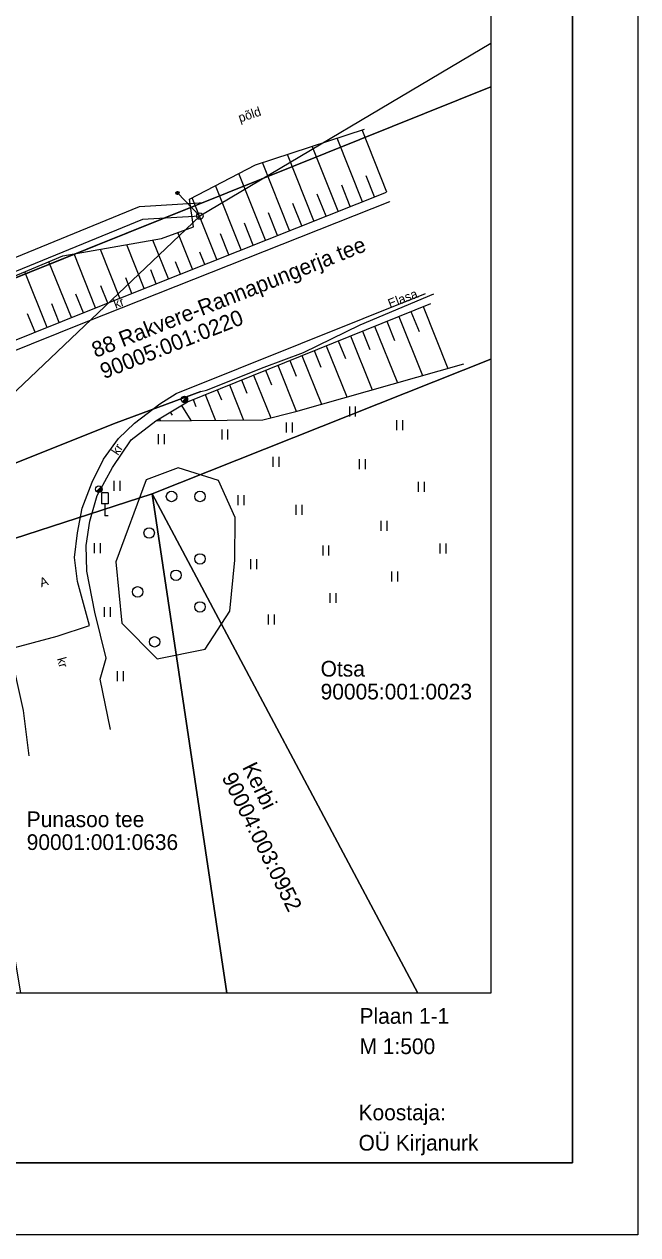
# Model space of a CAD drawing. Extents: x 655676 to 655781, y 6568872 to 6569021.
# Drawn here: x 655734.4 to 655781.4, y 6568872.1 to 6568964.7 of the extents above; entities that cross this region are included whole.
import ezdxf

# ---------------------------------------------------------------- set-up
doc = ezdxf.new("R2010")
doc.units = 0
for name, color, linetype in [('HALJASTUS', 7, 'Continuous'), ('KASUTUSALA', 7, 'Continuous'), ('LIIKLUS', 7, 'Continuous'), ('MPOHULIIN', 7, 'Continuous'), ('OL_SIDE', 7, 'Continuous'), ('PIIR', 7, 'Continuous'), ('POST', 7, 'Continuous'), ('PR_SIDE', 7, 'Continuous'), ('RELJEEF', 7, 'Continuous'), ('SITRASS', 7, 'Continuous'), ('TEE', 7, 'Continuous'), ('VORMISTUS', 7, 'Continuous')]:
    doc.layers.add(name, color=color, linetype=linetype)

msp = doc.modelspace()

# ---------------------------------------------------------------- linework, layer by layer
at = {"layer": 'HALJASTUS'}
for p, q in [((655759.288, 6568935.45), (655759.288, 6568934.689)), ((655759.743, 6568935.45), (655759.743, 6568934.689)), ((655754.44, 6568934.225), (655754.44, 6568933.464)), ((655754.895, 6568934.225), (655754.895, 6568933.464)), ((655762.911, 6568934.396), (655762.911, 6568933.635)), ((655763.366, 6568934.396), (655763.366, 6568933.635)), ((655744.644, 6568933.334), (655744.644, 6568932.573)), ((655745.099, 6568933.334), (655745.099, 6568932.573)), ((655749.509, 6568933.676), (655749.509, 6568932.915)), ((655749.964, 6568933.676), (655749.964, 6568932.915)), ((655753.431, 6568931.585), (655753.431, 6568930.824)), ((655753.886, 6568931.585), (655753.886, 6568930.824)), ((655760.045, 6568931.417), (655760.045, 6568930.656)), ((655760.5, 6568931.417), (655760.5, 6568930.656)), ((655741.241, 6568929.758), (655741.241, 6568928.997)), ((655741.696, 6568929.758), (655741.696, 6568928.997)), ((655764.563, 6568929.677), (655764.563, 6568928.916)), ((655765.018, 6568929.677), (655765.018, 6568928.916)), ((655750.746, 6568928.665), (655750.746, 6568927.904)), ((655751.201, 6568928.665), (655751.201, 6568927.904)), ((655755.189, 6568927.921), (655755.189, 6568927.16)), ((655755.644, 6568927.921), (655755.644, 6568927.16)), ((655761.712, 6568926.703), (655761.712, 6568925.942)), ((655762.167, 6568926.703), (655762.167, 6568925.942)), ((655739.746, 6568924.987), (655739.746, 6568924.226)), ((655740.202, 6568924.987), (655740.202, 6568924.226)), ((655766.215, 6568924.958), (655766.215, 6568924.197)), ((655766.671, 6568924.958), (655766.671, 6568924.197)), ((655757.245, 6568924.804), (655757.245, 6568924.043)), ((655757.7, 6568924.804), (655757.7, 6568924.043)), ((655751.719, 6568923.761), (655751.719, 6568922.999)), ((655752.174, 6568923.761), (655752.174, 6568922.999)), ((655762.514, 6568922.819), (655762.514, 6568922.058)), ((655762.969, 6568922.819), (655762.969, 6568922.058)), ((655757.794, 6568921.171), (655757.794, 6568920.41)), ((655758.249, 6568921.171), (655758.249, 6568920.41)), ((655740.51, 6568920.099), (655740.51, 6568919.338)), ((655740.965, 6568920.099), (655740.965, 6568919.338)), ((655753.073, 6568919.523), (655753.073, 6568918.762)), ((655753.528, 6568919.523), (655753.528, 6568918.762)), ((655741.493, 6568915.197), (655741.493, 6568914.436)), ((655741.948, 6568915.197), (655741.948, 6568914.436))]:
    msp.add_line(p, q, dxfattribs=at)
msp.add_lwpolyline([(655741.403, 6568923.562), (655741.853, 6568918.871), (655744.562, 6568916.139), (655748.235, 6568916.874), (655750.121, 6568919.789), (655750.513, 6568923.685), (655750.537, 6568926.943), (655749.264, 6568929.785), (655746.178, 6568930.741), (655743.73, 6568929.834)], close=True, dxfattribs=at)
for centre in [(655745.664, 6568928.56), (655747.844, 6568928.56), (655743.95, 6568925.767), (655747.844, 6568923.783), (655746.007, 6568922.533), (655743.068, 6568921.259), (655747.844, 6568920.108), (655744.366, 6568917.437)]:
    msp.add_circle(centre, 0.4, dxfattribs=at)
at = {"layer": 'KASUTUSALA'}
msp.add_lwpolyline([(655709.743, 6568937.057), (655743.212, 6568950.756), (655747.77, 6568951.021), (655748.021, 6568951.036), (655709.655, 6568935.641), (655709.573, 6568935.853)], close=True, dxfattribs=at)
at = {"layer": 'LIIKLUS'}
for p, q in [((655740.3, 6568928.84), (655740.3, 6568927.99)), ((655740.8, 6568928.84), (655740.3, 6568928.84)), ((655740.8, 6568928.84), (655740.8, 6568927.99)), ((655740.8, 6568927.99), (655740.3, 6568927.99)), ((655740.55, 6568927.99), (655740.55, 6568927.09)), ((655740.8, 6568927.09), (655740.55, 6568927.09))]:
    msp.add_line(p, q, dxfattribs=at)
at = {"layer": 'MPOHULIIN'}
msp.add_lwpolyline([(655770.139, 6568963.217), (655747.828, 6568950.023), (655716.621, 6568920.405), (655692.519, 6568890.558)], dxfattribs=at)
at = {"layer": 'OL_SIDE'}
msp.add_line((655770.139, 6568963.217), (655747.828, 6568950.023), dxfattribs=at)
at = {"layer": 'PIIR'}
for p, q in [((655687.639, 6568926.806), (655770.139, 6568959.911)), ((655770.139, 6568959.911), (655687.639, 6568926.806))]:
    msp.add_line(p, q, dxfattribs=at)
for points in [[(655687.639, 6568907.034), (655727.79, 6568923.46), (655744.18, 6568928.77), (655770.139, 6568939.075)], [(655770.139, 6568939.075), (655744.18, 6568928.77), (655764.524, 6568890.558)], [(655749.911, 6568890.558), (655744.18, 6568928.77), (655727.79, 6568923.46), (655731.26, 6568907.53), (655734.086, 6568890.558)], [(655764.524, 6568890.558), (655744.18, 6568928.77), (655749.911, 6568890.558)]]:
    msp.add_lwpolyline(points, dxfattribs=at)
at = {"layer": 'POST'}
for p, q in [((655746.471, 6568935.814), (655746.825, 6568936.167)), ((655739.922, 6568928.944), (655740.276, 6568929.297))]:
    msp.add_line(p, q, dxfattribs=at)
msp.add_lwpolyline([(655746.116, 6568951.787), (655747.828, 6568950.023)], dxfattribs=at)
for centre, radius in [((655746.116, 6568951.787), 0.125), ((655746.116, 6568951.787), 0.105), ((655746.116, 6568951.787), 0.0851), ((655746.116, 6568951.787), 0.0651), ((655746.116, 6568951.787), 0.0451), ((655746.116, 6568951.787), 0.0251), ((655746.116, 6568951.787), 0.00511), ((655747.828, 6568950.023), 0.25), ((655747.828, 6568950.023), 0.0234), ((655746.648, 6568935.991), 0.25), ((655740.099, 6568929.121), 0.25)]:
    msp.add_circle(centre, radius, dxfattribs=at)
for centre, radius, start, end in [((655746.648, 6568935.991), 0.225, 224.85406, 45.03563), ((655746.648, 6568935.991), 0.2, 224.84272, 45.04698), ((655746.648, 6568935.991), 0.175, 224.82813, 45.06157), ((655746.648, 6568935.991), 0.15, 224.80867, 45.08103), ((655746.648, 6568935.991), 0.125, 224.78144, 45.10826), ((655746.648, 6568935.991), 0.1, 224.74058, 45.14911), ((655746.648, 6568935.991), 0.075, 224.67249, 45.2172), ((655746.648, 6568935.991), 0.05, 224.53632, 45.35338), ((655746.648, 6568935.991), 0.025, 224.12776, 45.76193), ((655740.099, 6568929.121), 0.225, 224.85406, 45.03563), ((655740.099, 6568929.121), 0.2, 224.84272, 45.04698), ((655740.099, 6568929.121), 0.175, 224.82813, 45.06157), ((655740.099, 6568929.121), 0.15, 224.80867, 45.08103), ((655740.099, 6568929.121), 0.125, 224.78144, 45.10826), ((655740.099, 6568929.121), 0.1, 224.74058, 45.14911), ((655740.099, 6568929.121), 0.075, 224.67249, 45.2172), ((655740.099, 6568929.121), 0.05, 224.53632, 45.35338), ((655740.099, 6568929.121), 0.025, 224.12776, 45.76193)]:
    msp.add_arc(centre, radius, start, end, dxfattribs=at)
at = {"layer": 'PR_SIDE'}
msp.add_lwpolyline([(655747.828, 6568950.023), (655743.437, 6568949.768), (655710.653, 6568936.35), (655710.6, 6568935.972), (655716.621, 6568920.405)], dxfattribs=at)
at = {"layer": 'RELJEEF'}
for p, q in [((655762.147, 6568951.86), (655760.257, 6568956.613)), ((655760.289, 6568951.121), (655758.353, 6568955.989)), ((655756.572, 6568949.643), (655754.545, 6568954.74)), ((655758.43, 6568950.382), (655756.449, 6568955.364)), ((655754.713, 6568948.904), (655752.641, 6568954.116)), ((655752.855, 6568948.165), (655750.822, 6568953.277)), ((655761.218, 6568951.491), (655760.58, 6568953.094)), ((655750.996, 6568947.426), (655749.038, 6568952.35)), ((655759.359, 6568950.751), (655758.706, 6568952.393)), ((655749.138, 6568946.686), (655747.254, 6568951.424)), ((655755.642, 6568949.273), (655754.959, 6568950.991)), ((655757.501, 6568950.012), (655756.833, 6568951.692)), ((655753.784, 6568948.534), (655753.094, 6568950.269)), ((655751.926, 6568947.795), (655751.26, 6568949.468)), ((655745.421, 6568945.208), (655744.24, 6568948.177)), ((655747.28, 6568945.947), (655746.159, 6568948.764)), ((655750.067, 6568947.056), (655749.427, 6568948.666)), ((655739.846, 6568942.991), (655738.204, 6568947.121)), ((655741.704, 6568943.73), (655740.216, 6568947.473)), ((655743.563, 6568944.469), (655742.228, 6568947.825)), ((655748.209, 6568946.317), (655747.838, 6568947.25)), ((655737.989, 6568942.247), (655736.272, 6568946.525)), ((655746.35, 6568945.578), (655745.974, 6568946.523)), ((655736.133, 6568941.502), (655734.427, 6568945.753)), ((655742.633, 6568944.1), (655742.163, 6568945.283)), ((655744.492, 6568944.839), (655744.073, 6568945.893)), ((655740.775, 6568943.361), (655740.253, 6568944.673)), ((655738.917, 6568942.62), (655738.343, 6568944.05)), ((655735.205, 6568941.13), (655734.638, 6568942.542)), ((655737.061, 6568941.875), (655736.491, 6568943.296)), ((655764.006, 6568942.716), (655764.628, 6568941.174)), ((655764.934, 6568943.089), (655766.838, 6568938.365)), ((655761.224, 6568941.594), (655762.967, 6568937.27)), ((655762.151, 6568941.968), (655762.746, 6568940.493)), ((655763.079, 6568942.342), (655764.902, 6568937.818)), ((655759.369, 6568940.846), (655761.031, 6568936.723)), ((655760.296, 6568941.22), (655760.864, 6568939.812)), ((655756.586, 6568939.725), (655757.1, 6568938.45)), ((655757.514, 6568940.099), (655759.095, 6568936.175)), ((655758.441, 6568940.473), (655758.982, 6568939.131)), ((655754.731, 6568938.977), (655755.218, 6568937.77)), ((655755.659, 6568939.351), (655757.16, 6568935.628)), ((655751.949, 6568937.856), (655753.272, 6568934.573)), ((655752.876, 6568938.23), (655753.334, 6568937.095)), ((655753.804, 6568938.603), (655755.224, 6568935.08)), ((655750.094, 6568937.108), (655751.185, 6568934.401)), ((655751.021, 6568937.482), (655751.434, 6568936.458)), ((655747.311, 6568935.986), (655747.528, 6568935.448)), ((655748.239, 6568936.36), (655749.037, 6568934.381)), ((655749.166, 6568936.734), (655749.481, 6568935.953)), ((655746.423, 6568935.534), (655747.136, 6568934.363)), ((655744.715, 6568934.494), (655744.808, 6568934.341)), ((655745.569, 6568935.014), (655745.704, 6568934.793))]:
    msp.add_line(p, q, dxfattribs=at)
for points in [[(655713.696, 6568937.081), (655737.331, 6568946.968), (655744.898, 6568948.292), (655747.344, 6568949.208), (655747.034, 6568951.31), (655752.09, 6568953.935), (655760.438, 6568956.673)], [(655744.459, 6568934.338), (655752.661, 6568934.415), (655755.18, 6568935.068), (655768.051, 6568938.708)]]:
    msp.add_lwpolyline(points, dxfattribs=at)
at = {"layer": 'SITRASS'}
for points in [[(655695.26, 6568916.216), (655697.084, 6568916.967), (655698.793, 6568917.366), (655703.053, 6568919.085), (655708.166, 6568921.104), (655713.169, 6568923.052), (655717.253, 6568924.522), (655721.634, 6568926.369), (655725.324, 6568927.757), (655737.383, 6568932.592), (655741.419, 6568934.199), (655747.91, 6568936.591), (655748.343, 6568936.695), (655752.773, 6568938.454), (655755.777, 6568939.584), (655760.117, 6568941.693), (655765.75, 6568944.073)], [(655747.91, 6568936.591), (655741.419, 6568934.199), (655737.383, 6568932.592), (655725.324, 6568927.757), (655721.634, 6568926.369), (655717.286, 6568924.535)]]:
    msp.add_lwpolyline(points, dxfattribs=at)
at = {"layer": 'TEE'}
for points in [[(655693.19, 6568924.186), (655715.717, 6568933.306), (655739.408, 6568942.817), (655762.135, 6568951.855)], [(655762.389, 6568951.134), (655762.357, 6568951.121), (655739.091, 6568941.905), (655715.9, 6568932.599), (655692.679, 6568923.344)], [(655695.467, 6568916.284), (655718.708, 6568925.563), (655720.786, 6568926.384), (655723.41, 6568926.517), (655725.656, 6568925.794), (655727.541, 6568924.944), (655729.328, 6568923.657), (655730.716, 6568922.333), (655731.721, 6568920.681), (655732.603, 6568918.642), (655733.287, 6568916.889), (655736.912, 6568917.88), (655739.388, 6568918.688), (655738.457, 6568922.045), (655738.231, 6568923.878), (655738.471, 6568925.789), (655738.806, 6568927.658), (655739.583, 6568929.658), (655740.46, 6568931.421), (655741.605, 6568933.009), (655742.828, 6568934.162), (655744.758, 6568935.655), (655746.007, 6568936.453), (655765.124, 6568944.1)], [(655740.997, 6568910.72), (655740.199, 6568914.57), (655740.661, 6568916.194), (655739.779, 6568919.708), (655739.163, 6568922.844), (655739.121, 6568924.818), (655739.401, 6568926.666), (655739.975, 6568928.626), (655741.139, 6568930.779), (655742.583, 6568932.893), (655744.459, 6568934.338), (655746.881, 6568935.813), (655765.538, 6568943.333)], [(655734.756, 6568908.718), (655734.328, 6568912.19), (655733.287, 6568916.889), (655730.993, 6568920.088), (655729.104, 6568922.786), (655727.39, 6568923.82), (655725.405, 6568924.93), (655723.383, 6568925.551), (655721.328, 6568925.662), (655718.929, 6568925.108), (655697.184, 6568916.112)]]:
    msp.add_lwpolyline(points, dxfattribs=at)
at = {"layer": 'VORMISTUS'}
for points in [[(655676.389, 6569020.558), (655781.389, 6569020.558), (655781.389, 6568872.058), (655676.389, 6568872.058)], [(655681.389, 6568877.558), (655776.389, 6568877.558), (655776.389, 6569015.058), (655681.389, 6569015.058)], [(655681.389, 6569015.058), (655776.389, 6569015.058), (655776.389, 6568877.558), (655681.389, 6568877.558)], [(655770.139, 6568890.558), (655687.639, 6568890.558), (655687.639, 6568995.558), (655770.139, 6568995.558)]]:
    msp.add_lwpolyline(points, close=True, dxfattribs=at)

# ---------------------------------------------------------------- texts
at = {"layer": 'HALJASTUS'}
msp.add_text('põld', height=0.7, rotation=18.62257, dxfattribs=at).set_placement((655750.913, 6568957.176))
at = {"layer": 'PIIR'}
for s, rotation, p in [('88 Rakvere-Rannapungerja tee', 21.52538, (655739.846, 6568939.159)), ('90005:001:0220', 21.52538, (655740.488, 6568937.531)), ('Kerbi', 296.34401, (655751.055, 6568907.845)), ('90004:003:0952', 296.34401, (655749.486, 6568907.069))]:
    msp.add_text(s, height=1.2, rotation=rotation, dxfattribs=at).set_placement(p)
for s, p in [('Otsa', (655757.087, 6568914.778)), ('90005:001:0023', (655757.087, 6568913.028)), ('Punasoo tee', (655734.568, 6568903.257)), ('90001:001:0636', (655734.568, 6568901.507))]:
    msp.add_text(s, height=1.2, dxfattribs=at).set_placement(p)
at = {"layer": 'SITRASS'}
msp.add_text('Elasa', height=0.7, rotation=21.09647, dxfattribs=at).set_placement((655762.409, 6568942.959))
at = {"layer": 'TEE'}
for s, rotation, p in [('kr', 21.32326, (655741.384, 6568942.919)), ('kr', 55.61875, (655741.554, 6568931.659)), ('A', 18.91157, (655735.69, 6568921.605)), ('kr', 285.26874, (655736.881, 6568916.15))]:
    msp.add_text(s, height=0.7, rotation=rotation, dxfattribs=at).set_placement(p)
at = {"layer": 'VORMISTUS'}
for s, p in [('Plaan 1-1', (655760.068, 6568888.206)), ('M 1:500', (655760.068, 6568885.887)), ('Koostaja:', (655759.993, 6568880.819)), ('OÜ Kirjanurk', (655759.993, 6568878.5))]:
    msp.add_text(s, height=1.2, dxfattribs=at).set_placement(p)

doc.saveas('drawing.dxf')
